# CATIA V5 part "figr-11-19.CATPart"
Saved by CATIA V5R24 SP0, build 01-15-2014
Part number: Part1
Bounding box of the stored display mesh (mm): x -112.891 to 155.069, y -166 to 177, z -20.381 to 17.354
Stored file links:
  D:\KAVITA\CATIA V5-6R2014 Project_ Kavita\CATIA V5-6R2014_partfiles\Partfiles\c11_catia_v5-6r2014_prt\figr-11-19.CATPart
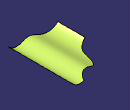
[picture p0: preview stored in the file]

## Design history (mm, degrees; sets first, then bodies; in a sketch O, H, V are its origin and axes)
Set1
  Sketch1 on zx-plane, origin (0, 0, 0), H (-1, 0, 0), V (0, 0, 1)
    spline S1 through (-155.0686, 17.3535) (-88.0787, 0) (-53.6625, 10.5338) (-6.5258, 0) (112.8909, 0)
    point P1 (-88.0787, 0)
    point P2 (-6.5258, 0)
    point P3 (112.8909, 0)
    coincidence: P1 H, P2 H, P3 H
  Extrude1: Element1 Sketch1, Lim1 177, Lim2 166, Direction zx-plane
  Sketch2 on xy-plane, origin (0, 0, 0), H (1, 0, 0), V (0, 1, 0)
    spline S1 through (-167.4699, -22.0252) (-66.0833, 12.4475) (-43.2893, 80.3989) (-11.0164, 123.7609) (37.393, 134.2276) (93.5198, 192.542)
  Extrude2: Element1 Sketch2, Lim1 94, Lim2 109, Direction xy-plane
  Trim1: Element1 Extrude1, Element2 Extrude2
  DatumSurface1
  DatumSurface2
  StUntrimFeature1 "CATStUntrimFeatureName": SpecToUntrim DatumSurface1
Body1 (main body)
